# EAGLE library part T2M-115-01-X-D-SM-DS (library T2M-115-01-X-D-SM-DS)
2MM SHROUDED TERMINAL ASSEMBLY, 30 PINS.
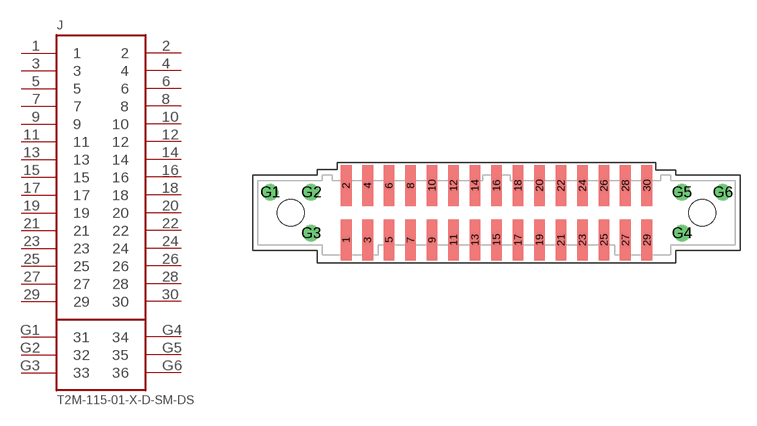
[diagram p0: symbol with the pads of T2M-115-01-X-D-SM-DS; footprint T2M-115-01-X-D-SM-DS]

Designator prefix J

## T2M-115-01-X-D-SM-DS  [T2M-115-01-X-D-SM-DS]
1  1
2  2
3  3
4  4
5  5
6  6
7  7
8  8
9  9
10  10
11  11
12  12
13  13
14  14
15  15
16  16
17  17
18  18
19  19
20  20
21  21
22  22
23  23
24  24
25  25
26  26
27  27
28  28
29  29
30  30
G1  31
G2  32
G3  33
G4  34
G5  35
G6  36

## Footprint T2M-115-01-X-D-SM-DS (pad centres in mm)
2MM SHROUDED TERMINAL ASSEMBLY, 30 PINS.
smd 1.02 x 3.8: 1 -14,-2.535; 2 -14,2.535; 3 -12,-2.535; 4 -12,2.535; 5 -10,-2.535; 6 -10,2.535; 7 -8,-2.535; 8 -8,2.535; 9 -6,-2.535; 10 -6,2.535; 11 -4,-2.535; 12 -4,2.535; 13 -2,-2.535; 14 -2,2.535; 15 0,-2.535; 16 0,2.535; 17 2,-2.535; 18 2,2.535; 19 4,-2.535; 20 4,2.535; 21 6,-2.535; 22 6,2.535; 23 8,-2.535; 24 8,2.535; 25 10,-2.535; 26 10,2.535; 27 12,-2.535; 28 12,2.535; 29 14,-2.535; 30 14,2.535
drill 1.02 pad 1.27 round: G1 -21.05,1.905; G2 -17.24,1.905; G3 -17.24,-1.905; G4 17.24,-1.905; G5 17.24,1.905; G6 21.05,1.905
hole 2.49 at -19.145,0
hole 2.49 at 19.145,0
